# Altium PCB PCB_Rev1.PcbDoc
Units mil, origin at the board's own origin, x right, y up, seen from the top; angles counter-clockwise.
Board outline 1770 x 990 mil, 4 copper layers (Top Layer, Layer 1 (GND), Layer 2 (PWR), Bottom Layer), stack 67.556 mil thick; 55 components, 43 nets, 231 pads, 78 vias.
Unrouted connection lines stored in the file: 55.
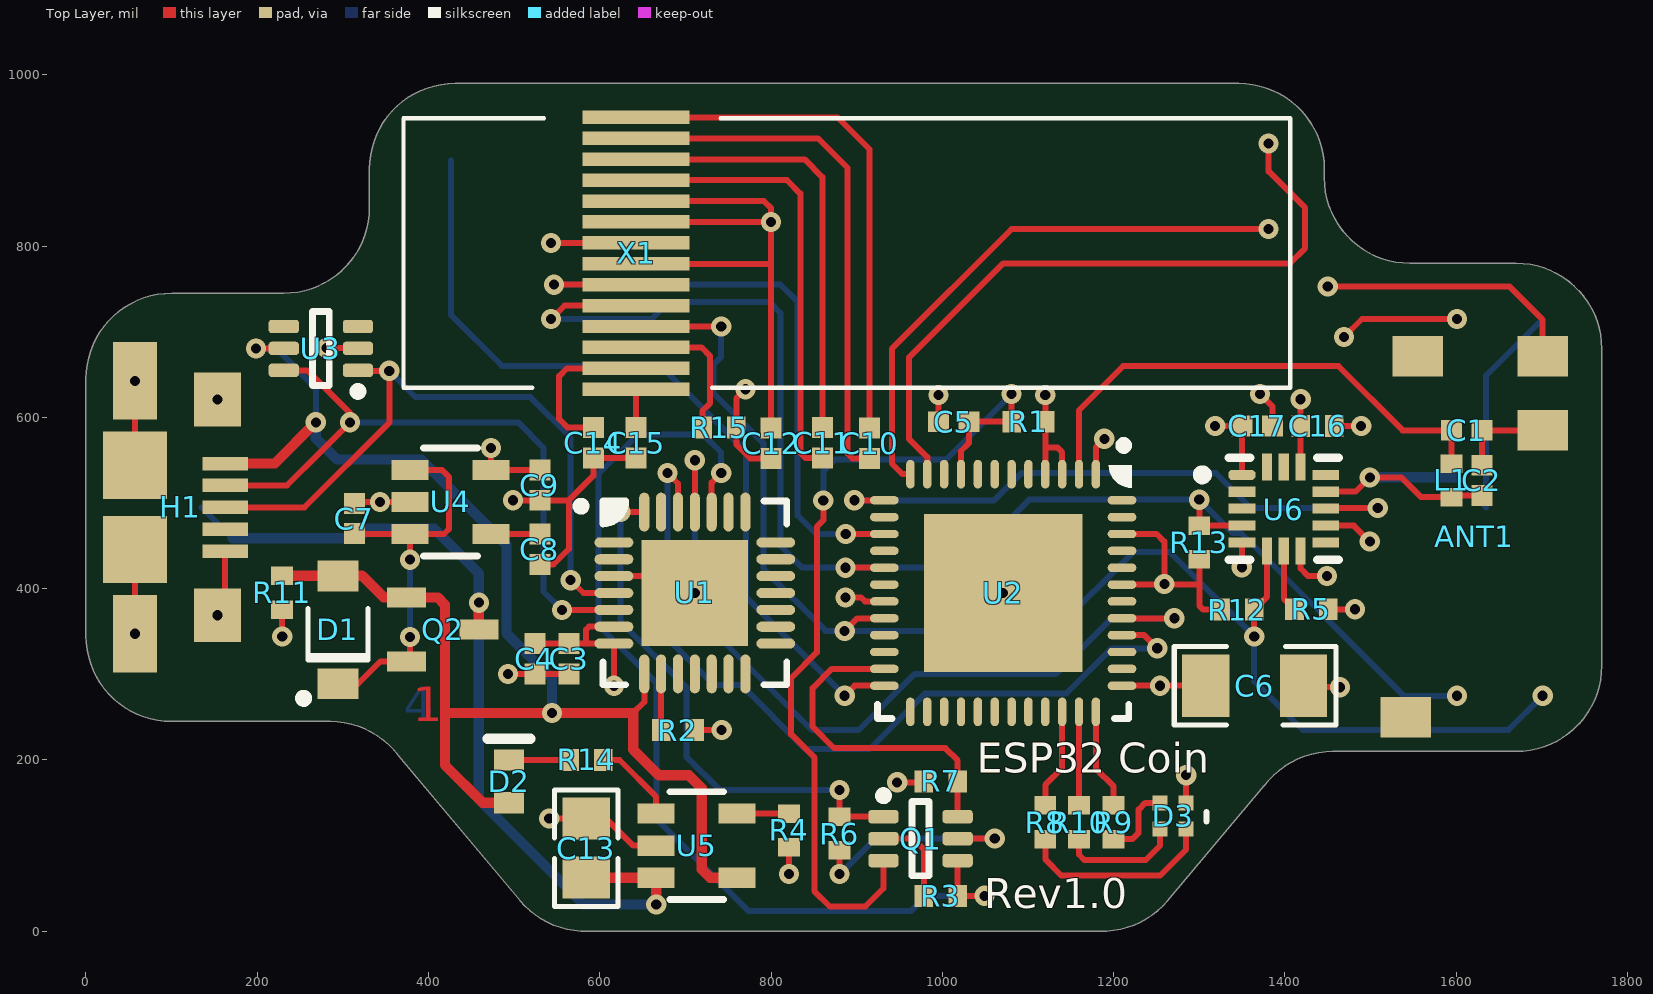
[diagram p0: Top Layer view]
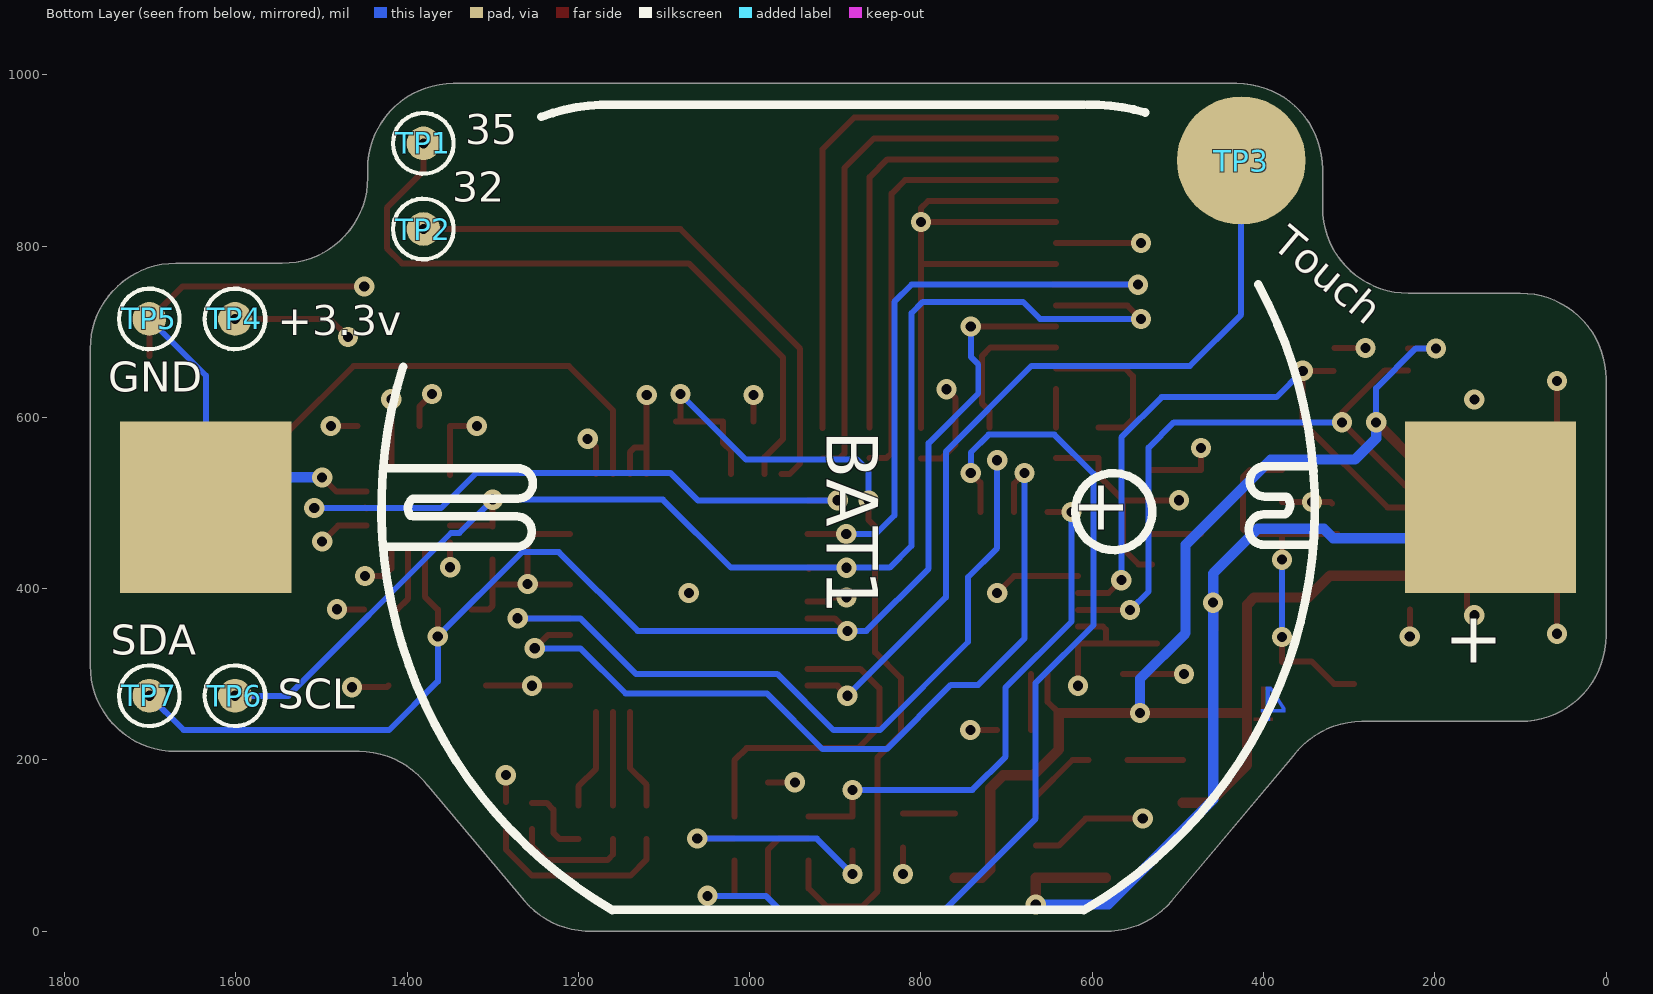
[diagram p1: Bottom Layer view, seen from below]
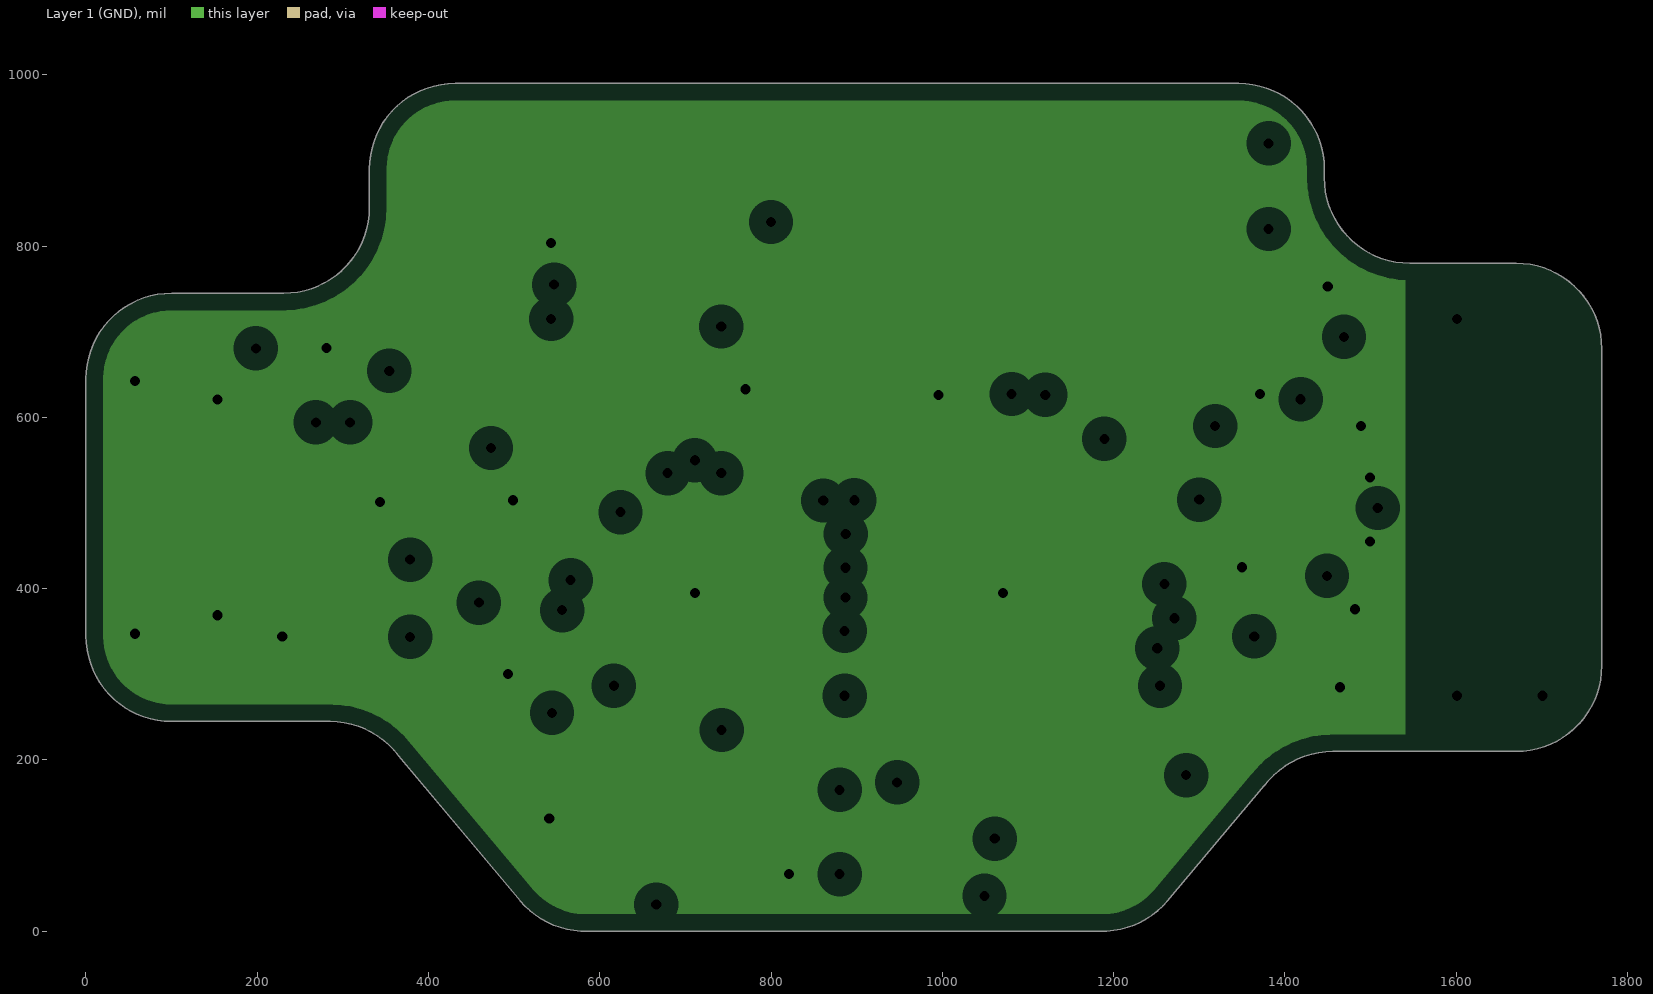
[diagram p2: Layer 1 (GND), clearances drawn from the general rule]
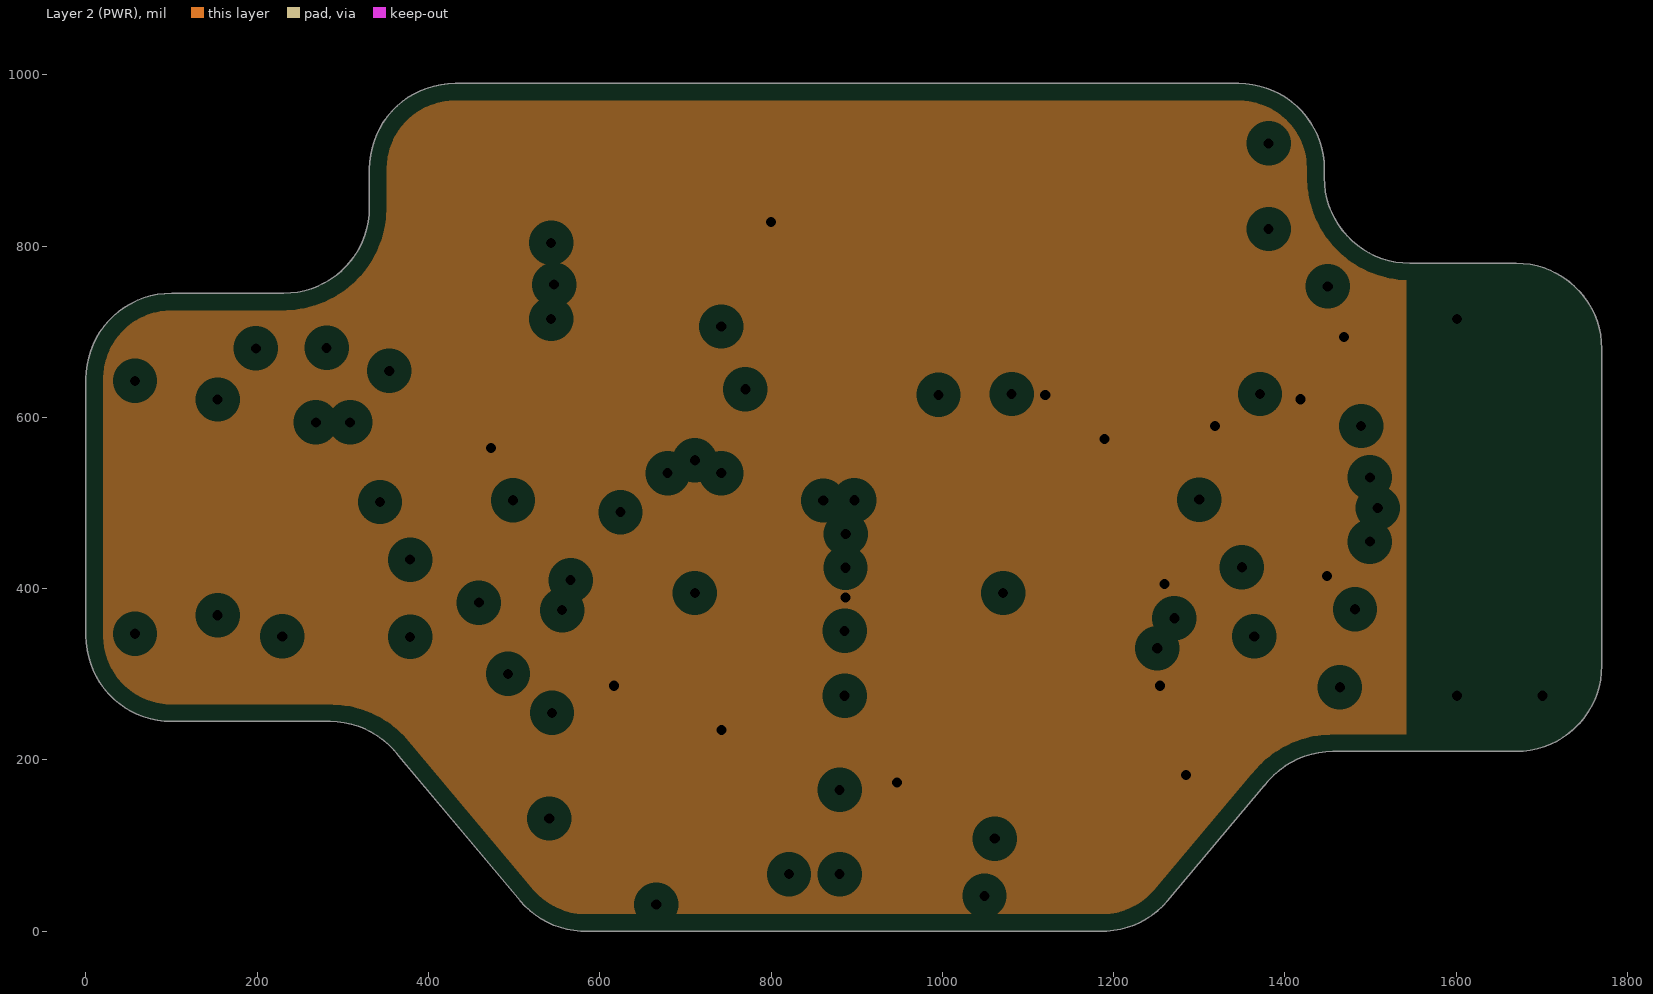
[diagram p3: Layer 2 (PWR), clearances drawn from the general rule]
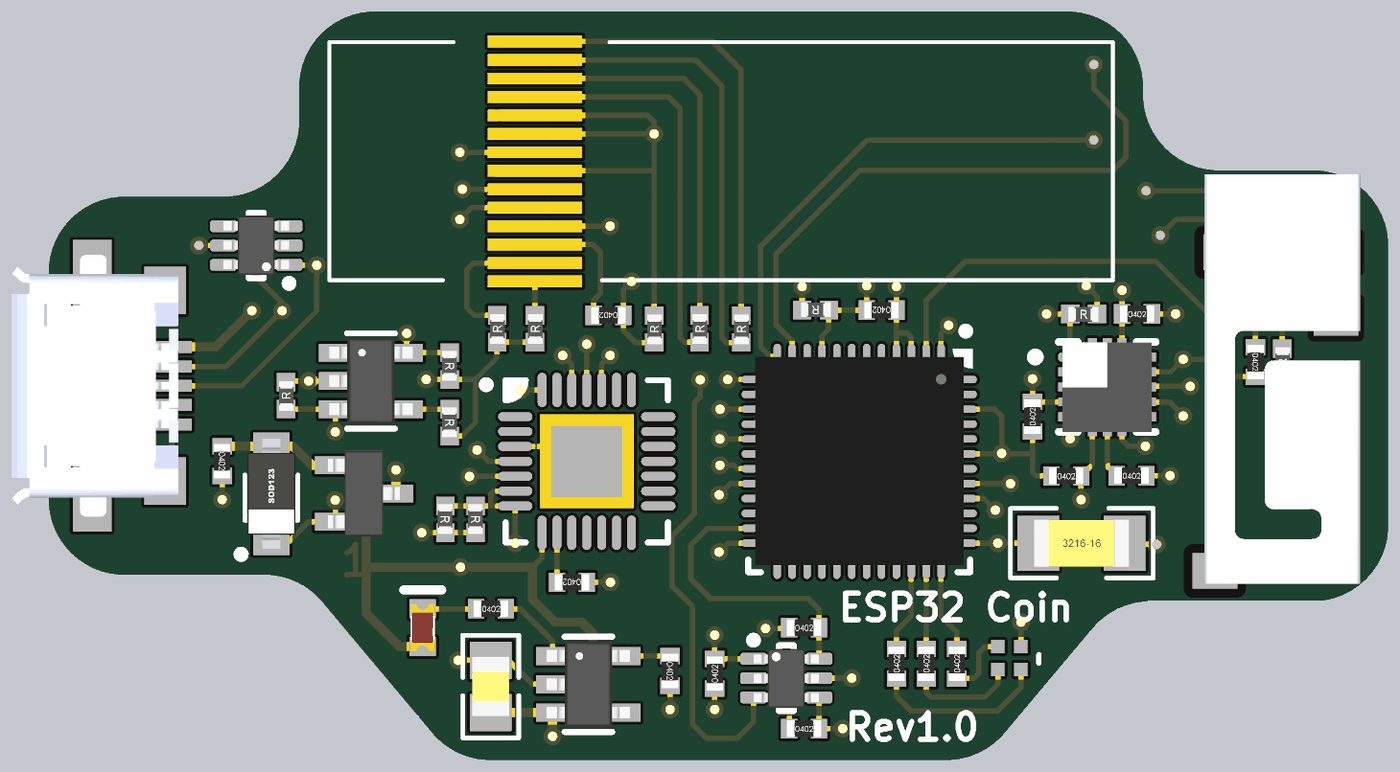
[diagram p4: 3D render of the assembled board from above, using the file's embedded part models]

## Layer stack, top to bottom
Top Solder: solder mask 0.4, Solder Resist, Dk 3.5
Top Layer: signal copper 1.4
Dielectric 2: prepreg 2.8, PP-006, Dk 4.1
Layer 1 (GND): plane copper 1.3779, net GND
Dielectric 1: dielectric 56.4, FR-4, Dk 4.8
Layer 2 (PWR): plane copper 1.3779, net +3.3V
Dielectric 3: prepreg 2.8, PP-006, Dk 4.1
Bottom Layer: signal copper 1.4
Bottom Solder: solder mask 0.4, Solder Resist, Dk 3.5

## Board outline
100,245 285,245 cw(c285,145) 365,205 507.44,35.24 506.98,35.69 ccw(c583.59,99.97) 586,0 1184,0 ccw(c1186.41,99.97) 1263.02,35.69 1262.55,35.24 1375.78,170.18 1376,170 cw(c1456,110) 1456,210 1670,210 ccw(c1670,310) 1770,310 1770,680 ccw(c1670,680) 1670,780 1546,780 cw(c1546,880) 1446,880 1446,890 ccw(c1346,890) 1346,990 431,990 ccw(c431,890) 331,890 331,845 cw(c231,845) 231,745 100,745 ccw(c100,645) 0,645 0,345 ccw(c100,345)

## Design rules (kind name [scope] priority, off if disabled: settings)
Clearance Clearance_H1 [All vs InComponent('H1')] p1: gap=9.5 ignorepadtopadclearanceinfootprint=FALSE
Clearance Clearance_U3 [All vs InComponent('U3')] p2: gap=9.5 ignorepadtopadclearanceinfootprint=FALSE
Clearance Clearance_Q1 [All vs InComponent('Q1')] p3: gap=9.5 ignorepadtopadclearanceinfootprint=FALSE
Clearance Clearance_X1 [All vs InComponent('X1')] p4: gap=8.5 ignorepadtopadclearanceinfootprint=FALSE
Clearance Clearance_U2 [All vs InComponent('U2')] p5: gap=9.5 ignorepadtopadclearanceinfootprint=FALSE
Clearance Clearance_U1 [All vs InComponent('U1')] p6: gap=7.8 ignorepadtopadclearanceinfootprint=FALSE
Clearance Clearance_U6 [All vs InComponent('U6')] p7: gap=7.5 ignorepadtopadclearanceinfootprint=FALSE
Clearance [All] p8: gap=10 ignorepadtopadclearanceinfootprint=FALSE except(0: Arc-Hole Track-Hole SMDPad-Hole THPad-Hole Via-Hole Fill-Hole Poly-Hole Region-Hole Text-Hole)
MinimumSolderMaskSliver MinimumSolderMaskSliver_X1 [All vs InComponent('X1')] p1: minsoldermaskwidth=0.6
MinimumSolderMaskSliver [All] p2: minsoldermaskwidth=1
PlaneClearance [All] p1: clearance=20
PlaneConnect [All] p1: planeconnectstyle=Relief reliefexpansion=20 reliefentries=4 reliefconductorwidth=10 reliefairgap=10
PolygonConnect [All] p1: connectstyle=Relief reliefconductorwidth=10 reliefentries=4 polygonreliefangle="90 Angle" airgapwidth=10
RoutingVias [All] p1: holewidth=11.81 width=23.62 viastyle="Through Hole" minholewidth=11.81 minwidth=23.62 maxholewidth=11.81 maxwidth=23.62
SilkToSilkClearance [All] p1: silktosilkclearance=5
SilkToSolderMaskClearance [IsPad] p1: minsilkscreentomaskgap=5 clearancetoexposedcopper=TRUE
SolderMaskExpansion [All] p1: expansion=4
Width [All] p1: maxlimit=12 minlimit=7 preferedwidth=7
25 further rules are at their usual default settings.

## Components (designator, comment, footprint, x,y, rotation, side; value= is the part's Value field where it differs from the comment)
ANT1 "RF ANT 2.4GHZ STAMPED MET SLD" PRO-OB-440 1701,671.61 r0 top locked
BAT1 "BATTERY-HOLDER (2450)" BU2450SM-JJ-GTR 885,495 r0 bottom locked value="Coin Cell Holder"
C1 "4.7pF" CAPC1005X56N 1612.28,585 r180 top
C2 "2.7pF" CAPC1005X56N 1630,526.5 r90 top
C3 "1uF" CAPC1005X56N 564.18,318.23 r270 top
C4 "1uF" CAPC1005X56N 524.18,318.23 r270 top
C5 "0.1uF" CAPC1005X56N 1013.28,595 r180 top
C6 "100uF" CAPC3216X160N 1364.78,286.73 r0 top
C7 "1uF" CAPC1005X56N 313.43,481.96 r90 top
C8 "10nF" CAPC1005X56N 530,446.18 r270 top
C9 "2.2uF" CAPC1005X56N 530,520.98 r270 top
C10 "1uF" CAPC1005X56N 915,570 r90 top
C11 "1uF" CAPC1005X56N 860,570.43 r90 top
C12 "1uF" CAPC1005X56N 800,570 r90 top
C13 "10uF" CAPC2012X140N 584.18,97.05 r90 top
C14 "4.7uF" CAPC1005X56N 592.5,570.43 r90 top
C15 "2.2uF" CAPC1005X56N 642.5,570.43 r90 top
C16 "0.1uF" RESC1005X40L 1438.08,590 r0 top
C17 "0.1uF" CAPC1005X56N 1367.61,590 r0 top
D1 "MBR0520-TP" SOD123 294.18,352 r90 top value=MBR0520
D2 "LED_0603" LED1608X55N-RED 494.18,175 r270 top value=Red
D3 "RGB" FC-B1010RGBT-HG 1269.44,134.67 r0 top
H1 "Micro USB" 1981584-1 110,495 r270 top locked
L1 "Inductor" RESC1005X40L 1594.57,526.5 r270 top value=1.8nH
Q1 "BC847S" SOT65P210X110-6N 974.57,107.21 r0 top
Q2 "FDN340P" SOT95P240X110-3N 416.51,352.4 r0 top value="Mosfet P-H"
R1 "10K" RESC1005X40L 1100.53,595 r180 top
R2 "1K" RESC1005X40L 691.31,235 r180 top
R3 "10K" RESC1005X40L 998.19,41.38 r0 top
R4 "10K" RESC1005X40L 821,117.72 r270 top
R5 "10K" RESC1005X40L 1430.87,376 r0 top
R6 "10K" RESC1005X40L 880,114.09 r90 top
R7 "10K" RESC1005X40L 998.19,175 r0 top
R8 "1K" RESC1005X40L 1120.21,127.28 r90 top
R9 "1K" RESC1005X40L 1200,127.28 r90 top
R10 "1K" RESC1005X40L 1159.58,127.28 r90 top
R11 "100K" RESC1005X40L 229.18,395.32 r270 top
R12 "4.7K" RESC1005X40L 1344.5,375.63 r0 top
R13 "4.7K" RESC1005X40L 1300,454.06 r90 top
R14 "2K" RESC1005X40L 584.5,200 r0 top
R15 "390K" RESC1005X40L 739.68,588.15 r180 top
TP1 "Test Point, 1mm Top Layer" TP100TL#1 1381,920 r90 bottom
TP2 "Test Point, 1mm Top Layer" TP100TL#1 1381,820 r90 bottom
TP3 "Test Point, 1mm Top Layer" TP100TL#2 401,925 r90 bottom
TP4 "Test Point, 1mm Top Layer" TP100TL#1 1601,715 r90 bottom
TP5 "Test Point, 1mm Top Layer" TP100TL#1 1701,715 r90 bottom
TP6 "Test Point, 1mm Top Layer" TP100TL#1 1601,275 r90 bottom
TP7 "Test Point, 1mm Top Layer" TP100TL#1 1701,275 r90 bottom
U1 "CP2102N" 28-QFN 711,395 r0 top
U2 "ESP32-PICO-D4" QFN48 1071,395 r270 top
U3 "PESD5V0L5UY" SOT65P210X110-6N 274.31,681.57 r180 top
U4 "SE5218ALG-LF" SOT95P280X144-5N 425.8,501.3 r0 top
U5 "SL4054ST25P" SOT95P280X144-5N 713.13,100 r0 top
U6 "ACCEL" QFN3X3_16_1.2 1398.68,492.99 r0 top
X1 "OLED_GLASS 96x16" "OLED_GLASS 96x16" 370.85,634.53 r180 top locked

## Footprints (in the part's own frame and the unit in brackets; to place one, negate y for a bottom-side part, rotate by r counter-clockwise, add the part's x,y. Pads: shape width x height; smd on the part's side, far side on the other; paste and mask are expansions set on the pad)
28-QFN [mm] "QFN, 28-Leads, Body 5.00x5.00mm, Pitch 0.50mm, Thermal Pad 3.15x3.15mm, IPC Medium Density"
  oval 1.15x0.3 smd: 1(-2.4,1.5) 2(-2.4,1) 3(-2.4,0.5) 4(-2.4,0) 5(-2.4,-0.5) 6(-2.4,-1) 7(-2.4,-1.5) 15(2.4,-1.5) 16(2.4,-1) 17(2.4,-0.5) 18(2.4,0) 19(2.4,0.5) 20(2.4,1) 21(2.4,1.5)
  oval 0.3x1.15 smd: 8(-1.5,-2.4) 9(-1,-2.4) 10(-0.5,-2.4) 11(0,-2.4) 12(0.5,-2.4) 13(1,-2.4) 14(1.5,-2.4) 22(1.5,2.4) 23(1,2.4) 24(0.5,2.4) 25(0,2.4) 26(-0.5,2.4) 27(-1,2.4) 28(-1.5,2.4)
  rect 3.15x3.15 smd paste-0.381: 29(0,0)
  silkscreen extent -3.5,-2.73 2.73,2.73, body extent -2.58,-2.57 2.57,2.58, height 1
1981584-1 [mm] "CONN RCPT MICRO USB TYPE AB"
  rect 0.4x1.35 smd: 1(-1.3,1.338) 2(-0.65,1.338) 3(0,1.338) 4(0.65,1.338) 5(1.3,1.338)
  rect 2.3x1.3 smd: 6(-3.75,-1.337) 6(3.75,-1.337)
  rect 1.6x1.4 smd: 6(-3.2,1.113) 6(3.2,1.113)
  rect 2x1.9 smd: 6(-1.25,-1.337) 6(1.25,-1.337)
  body extent -4.4,-4.05 4.4,1.55, height 2.75
BU2450SM-JJ-GTR [mil] "HOLDER,BATT,COIN,24.5MM,SMT"
  rect 200x200 smd: 1(-750,0) 2(750,0)
  silkscreen extent -545,-470 545,470, body extent -842,-570 3485,485, height 291
CAPC1005X56N [mm] "Chip Capacitor, 2-Leads, Body 1.0x0.5mm, IPC Medium Density (0402 ceramic)"
  rect 0.62x0.62 smd: 1(-0.45,0) 2(0.45,0)
  body extent -0.55,-0.3 0.55,0.3, height 0.6
CAPC2012X140N [mm] "Chip Capacitor, 2-Leads, Body 2.0x1.3mm, IPC Medium Density (0805 ceramic)"
  rect 1.25x1.4 smd: 1(-0.875,0) 2(0.875,0)
  silkscreen extent -1.73,-0.94 1.73,0.94, body extent -1,-0.62 1,0.63, height 1.24
CAPC3216X160N [mm] "Chip Capacitor, 2-Leads, Body 3.2x1.6mm, IPC Medium Density(C1206)"
  rect 1.4x1.85 smd: 1(-1.45,0) 2(1.45,0)
  silkscreen extent -2.39,-1.17 2.41,1.17, body extent -1.6,-0.8 1.6,0.8, height 1.89
FC-B1010RGBT-HG [mm] "LED,RGB,SMD,RoHS"
  rect 0.45x0.45 smd: 1(0.387,0.388) 2(0.387,-0.387) 3(-0.387,-0.387) 4(-0.387,0.388)
  silkscreen extent 0.99,-0.16 0.99,0.12, body extent -0.53,-0.55 0.53,0.58, height 1.2
LED1608X55N-RED [mil] "Chip LED RED, 2-Leads, Body 1.6x0.8mm, IPC Medium Density (0603 med)"
  rect 25x35 smd: 1(-25,0) 2(25,0)
  silkscreen extent -50,-25 -50,25, body extent -31,-16 31,16, height 24
"OLED_GLASS 96x16" [mm] "OLED_GLASS 96x16"
  rect 3.175x0.4 smd paste-2.54: 1(-6.9,-8.02) 2(-6.9,-7.4) 3(-6.9,-6.78) 4(-6.9,-6.16) 5(-6.9,-5.54) 6(-6.9,-4.92) 7(-6.9,-4.3) 8(-6.9,-3.68) 9(-6.9,-3.06) 10(-6.9,-2.44) 11(-6.9,-1.82) 12(-6.9,-1.2) 13(-6.9,-0.58) 14(-6.9,0.04)
  silkscreen extent -26.3,-8 0,0, body extent -26.3,-8 0,0, height 2
PRO-OB-440 [mm] "RF ANT 2.4GHZ STAMPED MET SLD"
  rect 1.5x1.2 smd mask+0.2: 1(0,0) 2(0,-2.2)
  rect 1.5x1.2 smd mask+0.3: 3(-3.7,0) 4(-4.064,-10.709)
  body extent -4.42,-11.14 7.98,2.61, height 3.56
QFN3X3_16_1.2 [mm] "QFN3X3_16_1.2"
  oct 0.8x0.3 smd: 1(-1.245,1.016)
  rect 0.8x0.3 smd: 2(-1.245,0.514) 3(-1.245,0.013) 4(-1.245,-0.489) 5(-1.245,-0.991) 9(1.245,-0.991) 10(1.245,-0.489) 11(1.245,0.013) 12(1.245,0.514) 13(1.245,1.016)
  rect 0.3x0.8 smd: 6(-0.495,-1.245) 7(0,-1.245) 8(0.495,-1.245) 14(0.495,1.245) 15(0,1.245) 16(-0.495,1.245)
  silkscreen extent -2.54,-1.5 1.63,1.52, body extent -1.51,-1.5 1.51,1.5, height 0.81
QFN48 [mm] "QFN, 48-Leads, Body 7x7mm, Pitch 0.5mm, IPC Medium Density"
  oval 0.85x0.25 smd: 1(-3.525,2.75) 2(-3.525,2.25) 3(-3.525,1.75) 4(-3.525,1.25) 5(-3.525,0.75) 6(-3.525,0.25) 7(-3.525,-0.25) 8(-3.525,-0.75) 9(-3.525,-1.25) 10(-3.525,-1.75) 11(-3.525,-2.25) 12(-3.525,-2.75) 25(3.525,-2.75) 26(3.525,-2.25) 27(3.525,-1.75) 28(3.525,-1.25) 29(3.525,-0.75) 30(3.525,-0.25) 31(3.525,0.25) 32(3.525,0.75) 33(3.525,1.25) 34(3.525,1.75) 35(3.525,2.25) 36(3.525,2.75)
  oval 0.25x0.85 smd: 13(-2.75,-3.525) 14(-2.25,-3.525) 15(-1.75,-3.525) 16(-1.25,-3.525) 17(-0.75,-3.525) 18(-0.25,-3.525) 19(0.25,-3.525) 20(0.75,-3.525) 21(1.25,-3.525) 22(1.75,-3.525) 23(2.25,-3.525) 24(2.75,-3.525) 37(2.75,3.525) 38(2.25,3.525) 39(1.75,3.525) 40(1.25,3.525) 41(0.75,3.525) 42(0.25,3.525) 43(-0.25,3.525) 44(-0.75,3.525) 45(-1.25,3.525) 46(-1.75,3.525) 47(-2.25,3.525) 48(-2.75,3.525)
  rect 4.7x4.7 smd paste-0.5: 49(0,0)
  silkscreen extent -4.5,-3.72 3.72,3.81, body extent -3.52,-3.51 3.5,3.51, height 0.78
RESC1005X40L [mm] "Chip Resistor, 2-Leads, Body 1.0x0.5mm, IPC Medium Density (0402)"
  rect 0.55x0.65 smd: 1(-0.5,0) 2(0.5,0)
  body extent -0.57,-0.27 0.58,0.28, height 0.41
SOD123 [mil] "Molded Diode, 2-Leads, Body 2.85x1.8mm, IPC Medium Density (SOD123)"
  rect 36x48 smd: 1(-63,0) 2(63,0)
  silkscreen extent -85,-35 25,45, body extent -73,-31 73,31, height 50
SOT65P210X110-6N [mm] "SC70, 6-Leads, Body 2.4x2.2mm (max), Pitch 0.65mm, IPC Medium Density"
  rrect50% 0.9x0.4 smd mask+0.076: 1(-1.1,0.675) 2(-1.1,0.025) 3(-1.1,-0.625) 4(1.1,-0.625) 5(1.1,0.025) 6(1.1,0.675)
  silkscreen extent -1.22,-1.07 0.25,1.42, body extent -1.1,-0.97 1.1,1.01, height 0.99
SOT95P240X110-3N [mm] "SOT23, 3-Leads, Body 3.0x2.5mm (max), Pitch 0.95mm, IPC Medium Density"
  rect 1.15x0.6 smd: 1(-1.075,0.95) 2(-1.075,-0.95) 3(1.075,0)
  body extent -1.2,-1.45 1.2,1.45, height 0.99
SOT95P280X144-5N [mm] "SOT23, 5-Leads, Body 3.1x3.0mm (max), Pitch 0.95mm, IPC Medium Density (RFMD SOT23-5)"
  rect 1.1x0.6 smd: 1(-1.2,0.95) 2(-1.2,0) 3(-1.2,-0.95) 4(1.2,-0.95) 5(1.2,0.95)
  silkscreen extent -0.8,-1.6 0.8,1.6, body extent -1.4,-1.45 1.4,1.45, height 1.45
TP100TL#1 [mm] "Test Point"
  round 1 smd paste-0.5 mask+0.076: 1(0,0)
  silkscreen extent -0.9,-0.9 0.9,0.9
TP100TL#2 [mm] "Test Point"
  round 3.81 smd paste-0.5 mask+0.076: 1(-0.635,0.635)

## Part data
ANT1: library part PRO-OB-440, Manufacturer="Proant AB"
BAT1: library part BU2450SM-JJ-GTR, "HOLDER,BATT,COIN,24.5MM,SMT", Manufacturer=MPD
C1: library part CAP_0402, "CAP CER 47pF 50V 0402", Manufacturer=Huaxin, PartNumber=0603N4R7C500CT
C2: library part CAP_0402, "CAP CER 2.7pF 50V 0402", Manufacturer=Huaxin, PartNumber=0603N2R7C500
C3 C4 C7 C10 C11 C12: library part CAP_0603, "CAP CER 1uF 16V 0402", Manufacturer=Murata, PartNumber=GRM155R61C105KA12D
C5 C16 C17: library part CAP_0402, "CAP CER 0.1uF 16V 0402", Manufacturer=CCTC, PartNumber=TCC0402X5R104M160AT
C6: library part CAP_1206, "CAP CER 100uF 6.3V 1206", Manufacturer="Taiyo Yuden", PartNumber=JMK316BJ107ML-T
C8: library part CAP_0603, "CAP CER 10nF 0402", Manufacturer=Murata, PartNumber=GRM155R71C103JA01D
C9 C15: library part CAP_0402, "CAP CER 2.2uF 16V 0402", Manufacturer=Samsung, PartNumber=CL05A225KO5NQNC
C13: library part CAP_0805, "CAP CER 10uF 16V 0805", Manufacturer=Samsung, PartNumber=CL21A106KOQNNNG
C14: library part CAP_0603, "CAP CER 4.7uF 16V 0402", Manufacturer=Kyocera, PartNumber=CM05X5R475M16AH
D1: "DIODE SCHOTTKY 20V 500MA SOD123", Manufacturer=CJ, PartNumber=MBR0520
D2: "LED RED CLEAR 0603 SMD", Manufacturer=FNO, PartNumber=FC-DA1608HRK-620D
D3: library part FC-B1010RGBT-HG, "LED,RGB,SMD,RoHS", Manufacturer=Foshan
H1: library part 1981584-1, "CONN RCPT MICRO USB TYPE AB", Manufacturer="REG CON", PartNumber=C21377
L1: "Inductor 1.8nH 0402", Manufacturer=GFBE, PartNumber=BKW0603UC1N8KGT
Q1: "TRANS 2NPN 44V 0.1A SC-70-6", Manufacturer=Changjiang
Q2: "MOSFET P-CH 20V 2A SOT-23", Manufacturer="On Semi"
R1 R3 R6 R7: library part RES_0402, "RES SMD 10K OHM 0402", Manufacturer=Guangdong, PartNumber=RC-02W1002FT
R2: library part RES_0603, "RES SMD 1K OHM 0402", Manufacturer=Yageo, PartNumber=RC0402FR-071KL
R4: library part RES_0603, "RES SMD 10K OHM 1% 1/10W 0402", Manufacturer=Guangdong, PartNumber=RC-02W1002FT
R5: library part RES_0603, "RES SMD 10K OHM 0402", Manufacturer=Guangdong, PartNumber=RC-02W1002FT
R8 R9 R10: library part RES_0402, "RES SMD 1K OHM 1% 1/10W 0402", Manufacturer=Yageo, PartNumber=RC0402FR-071KL
R11: library part RES_0603, "RES SMD 100K OHM 0402", Manufacturer="Uniroyal Elec", PartNumber=0402WGF1003TCE
R12: library part RES_0603, "RES SMD 4.7K OHM 0402", Manufacturer="TA-I Tech", PartNumber=RM04FTN4701
R13: library part RES_0603, "RES SMD 4.7K OHM 0402", Manufacturer="HK Resistors", PartNumber=RM04FTN4701
R14: library part RES_0603, "RES SMD 2K OHM 1% 1/10W 0402", Manufacturer="LIZ Elec", PartNumber=CR0402FF2001G
R15: library part RES_0603, "RES SMD 390K OHM 0402", Manufacturer=Guangdong, PartNumber=RC-02W3903FT
TP1 TP2 TP3 TP4 TP5 TP6 TP7: Manufacturer=N/A
U1: "IC BRIDGE USB TO UART 28QFN", Manufacturer="Silicon Labs", PartNumber=CP2102N-A01-GQFN28
U2: "RF Transceiver ICs QFN-48_7x7x05P RoHS", Manufacturer=Espressif
U3: "TVS SOT-363 RoHS", Manufacturer=Yenji
U4: "IC REG LDO 3.3V 0.5A SOT23-5", Manufacturer=Seaward
U5: "Charger IC Lithium-Ion/Polymer SOT23-5", Manufacturer=Techfuse
U6: library part E-05-177, "IC,ACCEL,2-16G I2C/SPI,16LGA,RoHS"
X1: "96x16 OLED_GLASS", Manufacturer=N/A, PartNumber=ER-OLED0.69-1W

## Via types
v1: diameter 23.62, hole 11.81, Top Layer to Bottom Layer, tented both sides, 77 vias
v2: diameter 23.62, hole 11.81, Top Layer to Bottom Layer, 1 vias

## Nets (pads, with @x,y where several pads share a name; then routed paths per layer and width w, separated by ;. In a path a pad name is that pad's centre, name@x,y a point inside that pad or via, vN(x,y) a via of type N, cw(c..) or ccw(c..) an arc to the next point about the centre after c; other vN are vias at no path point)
+3.3V: C3.1 C4.1 C6.1 C9.1 C12.2 C16.1 C17.1 D3.1 R1.1 R2.1 R7.1 R12.1 R13.1 TP4.1 U1.6 U1.7 U2.1 U2.3 U2.4 U2.19 U2.37 U2.43 U2.46 U4.5 U6.1 U6.8 U6.14 X1.5 X1.6 X1.8 | length 2069
  Top Layer w7: v1(473.05,564.25) U4.5 C9.1 ; C4.1 C3.1 584.18,335.95 ; v1(616.51,286.73) U1.7 584.18,335.95 ; U1.6 587.41,355.63 584.18,352.4 584.18,335.95 ; X1.8 798.31,779.41 800,777.72 ; X1.6 v1(800,828.23) ; X1.5 791.76,852.64 800,844.4 v1(800,828.23) ; R2.1 v1(742.3,235) ; C12.2 v1(800,828.23) ; v1(886.88,389.8) 905.21,389.8 909.85,385.16 U2.19 ; v1(947.26,173.9) R7.1@978.56,173.9 ; U2.4 1120.21,565 ; v1(1120.21,626.3) R1.1 1120.21,565 ; U2.3 1139.9,559.29 1134.18,565 1120.21,565 ; U2.1 1179.27,565.08 v1(1189.18,575) ; U2.37 C6.1 ; U2.43 1300,404.84 ; U2.46 1250.29,463.9 1259.18,455 v1(1259.18,405.5) ; D3.1@1284.7,151.02 v1(1284.7,182.32) ; R13.1 1300,380.19 1304.56,375.63 R12.1 ; v1(1318.6,590) C17.1 1349.68,589.79 U6.1 ; U6.8 1418.18,423.68 1426.87,415 v1(1449.18,415) ; U6.14 1418.18,589.79 C16.1 v1(1418.4,621.3) ; v1(1469,694) 1490,715 v1(1601,715)
  other v1: 1254.18,286.73
BLUE: R8.2 U2.34 | length 117.4
  Top Layer w7: R8.2 1120.21,171.03 1139.9,190.71 U2.34
D+: H1.3 U1.4 U3.1 | length 800.9
  Top Layer w7: H1.3 255.19,495 354.18,594 v1(354.18,654.41) U3.1@318.2,654.41 ; v1@570.6,410 v1(566,410) 581,395 U1.4
  Bottom Layer w7: v1(354.18,654.41) 384.89,623.7 518.97,623.7 566,576.68 v1(566,410)
D-: H1.2 U1.5 U3.6 | length 790.8
  Top Layer w7: H1.2 234.78,520.59 273.43,559.25 v1(308.43,594.25) 308.43,604.97 258.4,655 U3.6 ; v1(556,375) 616.2,375 U1.5
  Bottom Layer w7: v1(308.43,594.25) 504.73,594.25 534.18,564.79 534.18,396.81 v1(556,375) v1@556,383.19
DTR: Q1.1 R6.2 U1.28 | length 622.7
  Top Layer w7: v1(624.18,489.49) U1.28 ; v1(880,165.08) R6.2 Q1.1
  Bottom Layer w7: v1(624.18,489.49) 624.18,361.62 701,284.8 701,204 739.92,165.08 v1(880,165.08)
EN: C5.1 Q1.3 R1.2 U2.9 | length 1054.8
  Top Layer w7: v1(861,503) 861,480 853.56,472.56 853.56,325.68 823.56,295.68 823.56,230 850.56,203 850.56,46.9 868.56,28.9 910,28.9 931.26,50.16 Q1.3 ; U2.9 1021.79,560.79 1031,570 C5.1 R1.2 R1.2@1085.84,595 ; R1.2@1080.84,596.1 v1(1080.84,627.4)
  Bottom Layer w7: v1(861,503) 861,537.24 874.56,550.81 1004.25,550.81 v1(1080.84,627.4)
GND: ANT1.1 BAT1.2 C2.1 C3.2 C4.2 C5.2 C6.2 C7.2 C8.2 C9.2 C12.1 C13.2 C14.1 C15.1 C16.2 C17.2 H1.5 H1.6 L1.2 R4.2 R5.2 R11.2 R15.1 TP5.1 U1.3 U1.29 U2.49 U3.2 U4.2 U5.2 U6.5 U6.10 U6.12 X1.7 | length 2411
  Top Layer w7: v1(57.34,347.36) H1.6@57.34,445.79 ; H1.6@57.34,544.21 v1(57.34,642.64) ; v1(153.8,369.02) 162.66,377.87 H1.5 ; v1(229.18,344.33) R11.2 ; v1(281.04,681.18) U3.2@317.02,681.18 ; C7.2@319.91,499.25 321.97,501.3 U4.2 ; v1(492.89,300.51) C4.2 C3.2 ; v1(498.7,503.27) C9.2 563.87,503.27 ; C8.2 545.96,428.46 563.87,446.37 563.87,503.27 ; v1(541,131.73) 583.95,131.73 C13.2 607.69,131.5 639.18,100 U5.2 ; v1(543.18,803.82) X1.7 ; U1.3 691.31,414.69 v1(711,395) ; C15.1 C14.1 592.5,531.9 563.87,503.27 ; v1(770.06,632.95) 759.37,622.27 R15.1 759.37,568.4 775.49,552.28 C12.1 ; v1(821,66.73) R4.2 ; C5.2 v1(995.57,626.3) ; v1(1349.68,425.03) U6.5 ; v1(1370.92,627.4) 1385.33,612.99 C17.2 ; C6.2 1423.6,285 v1(1464.18,285) ; U6.10 1480.44,473.74 v1(1499.18,455) ; U6.12 1482.43,513.24 v1(1499.18,530) 1536,530 1559.19,506.81 L1.2 1596.54,508.78 C2.1 ; v1(1450,753) 1662,753 1701,714 ANT1.1 ; R5.2 v1(1481.85,376) ; C16.2 v1(1489.07,590)
  Bottom Layer w7: BAT1.2@1600,530 BAT1.2 1635,649 TP5.1
  Bottom Layer w12: v1(1499.18,530) BAT1.2@1600,530
  other v1: 343.43,501.3 153.8,620.98
  other v2: 1071,395
GPIO32: TP2.1 U2.12 | length 658.6
  Top Layer w7: U2.12 953.48,533.78 941,546.26 941,680 1081,820 v1(1381,820)
GPIO35: TP1.1 U2.11 | length 800.4
  Top Layer w7: U2.11 982.42,553.58 961,575 961,669.7 1071.3,780 1406,780 1423.6,797.6 1423.6,844.8 1381,887.4 v1(1381,920)
GREEN: R10.2 U2.35 | length 109.3
  Top Layer w7: R10.2 U2.35
INT1: U2.13 U6.11 | length 738.4
  Top Layer w7: v1(897.22,503.27) U2.13 ; U6.11 U6.11@1448.44,494.25 ; U6.11@1449.19,495 U6.11@1448.44,494.25 ; v1(1508.43,494.25) U6.11@1448.44,494.25
  Bottom Layer w7: v1(897.22,503.27) 1060.55,503.27 1092.28,535 1319.49,535 1360.24,494.25 v1(1508.43,494.25)
IO0: Q1.6 R7.2 U2.23 | length 389.4
  Top Layer w7: U2.23 871.08,306.42 848.56,283.9 848.56,238.9 873.56,213.9 1003.56,213.9 1017.87,199.58 R7.2 Q1.6
NetANT1_2: ANT1.2 C1.1 C2.2 | length 111.8
  Top Layer w7: C2.2 C1.1 ANT1.2
NetC1_2: C1.2 L1.1 U2.2 | length 600.8
  Top Layer w7: U2.2 1159.58,608.35 1211.23,660 1462.46,660 1537.46,585 C1.2 L1.1
NetC8_1: C8.1 U4.4 | length 57
  Top Layer w7: U4.4 C8.1
NetC10_1: C10.1 X1.2 | length 622.5
  Top Layer w7: X1.2 854.78,925.87 889.3,891.35 889.3,557.99 895,552.28 C10.1
NetC10_2: C10.2 X1.1 | length 613.3
  Top Layer w7: X1.1 877.87,950.28 915,913.15 C10.2
NetC11_1: C11.1 X1.4 | length 529.3
  Top Layer w7: X1.4 818.6,877.05 834.3,861.35 834.3,558.42 840,552.72 C11.1
NetC11_2: C11.2 X1.3 | length 518.6
  Top Layer w7: X1.3 839.19,901.46 860,880.65 C11.2
NetC14_2: C14.2 X1.13 | length 188
  Top Layer w7: C14.2 562.5,588.15 552.5,598.15 552.5,648.15 561.71,657.36 X1.13
NetC15_2: C15.2 X1.14 | length 44.8
  Top Layer w7: C15.2 X1.14
NetD2_1: D2.1 R14.1 | length 64.8
  Top Layer w7: D2.1 R14.1@559,200
NetD3_2: D3.2 R8.1 | length 232.5
  Top Layer w7: R8.1 1120.21,83.97 1139.18,65 1254.18,65 1284.7,95.51 D3.2
NetD3_3: D3.3 R10.1 | length 141.6
  Top Layer w7: R10.1 1159.58,89.6 1165.91,83.27 1237.46,83.27 1254.18,100 D3.3
NetD3_4: D3.4 R9.1 | length 87.5
  Top Layer w7: R9.1 1221.78,107.6 1229.18,115 1229.18,141.97 1237.14,149.92 D3.4
NetQ1_2: Q1.2 R3.1 | length 106.7
  Top Layer w7: Q1.2 966,108.19 978.5,95.68 R3.1
NetQ1_5: Q1.5 R6.1 | length 269.3
  Top Layer w7: v1(880,66.73) R6.1 ; Q1.5 v1(1061.16,108.19)
  Bottom Layer w7: v1(880,66.73) 921.46,108.19 v1(1061.16,108.19)
NetR2_2: R2.2 U1.9 | length 65.5
  Top Layer w7: R2.2 U1.9
NetR4_1: R4.1 U5.5 | length 60.6
  Top Layer w7: U5.5 R4.1
NetR5_1: R5.1 U6.7 | length 73.2
  Top Layer w7: U6.7 1398.68,388.5 R5.1
NetR14_2: R14.2 U5.1 | length 99.2
  Top Layer w7: R14.2 622.97,200 665.88,157.09 U5.1
NetR15_2: R15.2 X1.12 | length 177.7
  Top Layer w7: X1.12 718.72,681.77 728.88,671.61 728.88,616.59 720,607.72 R15.2
OLED_RESET: U2.15 X1.9 | length 751.6
  Top Layer w7: v1(546.68,755) X1.9@646,755 ; v1(887.18,463.9) U2.15
  Bottom Layer w7: v1(546.68,755) 811,755 831,735 831,485.5 852.6,463.9 v1(887.18,463.9)
RED: R9.2 U2.36 | length 117.8
  Top Layer w7: U2.36 1179.27,189.92 1200,169.19 R9.2
RTS: Q1.4 R3.2 U1.24 | length 1183.4
  Top Layer w7: U1.24 730.68,523.86 v1(741.82,535) ; Q1.4 R3.2 v1(1049.17,41.38)
  Bottom Layer w7: v1(741.82,535) 741.82,559.09 720.92,580 644.18,580 598.56,534.37 598.56,357.44 666,290 666,131.44 773.55,23.9 963.56,23.9 981.04,41.38 v1(1049.17,41.38)
RXD: U1.26 U2.40 | length 973.1
  Top Layer w7: v1(679.18,535) 691.31,522.87 U1.26 ; U2.40 1235.6,345.79 v1(1250.92,330.47) v1@1250.92,338.27
  Bottom Layer w7: v1(679.18,535) 679.18,341.62 733.09,287.72 765,287.72 840,212.72 915,212.72 980,277.72 1145,277.72 1197.76,330.47 v1(1250.92,330.47)
SCL: R13.2 TP6.1 U2.17 U6.4 X1.10 | length 1715.2
  Top Layer w7: v1(543.18,715) 558.77,730.59 X1.10 ; v1(886.88,424.53) U2.17@931.92,424.53 ; U2.17@930.96,423.27 U2.17 ; R13.2@1300,472.72 R13.2 ; v1(1300,504.02) R13.2 ; U6.4 R13.2
  Bottom Layer w7: v1(543.18,715) 660.88,715 680.88,735 797.72,735 811,721.72 811,450.03 836.5,424.53 v1(886.88,424.53) 1021.81,424.53 1101.3,504.02 v1(1300,504.02) 1339.02,465 1348.72,465 1538.72,275 v1(1601,275)
SDA: R12.2 TP7.1 U2.20 U6.6 X1.11 | length 1682
  Top Layer w7: X1.11 v1(741.82,706.18) ; v1@885.92,353.15 v1(885.92,350.71) 900.68,365.47 U2.20 ; v1(1364.18,344.33) R12.2 1379.18,390.63 U6.6
  Bottom Layer w7: v1(741.82,706.18) 741.82,670.82 733.09,662.09 733.09,627.91 791,570 791,423.46 863.76,350.71 v1(885.92,350.71) 1130.71,350.71 1222.72,442.72 1265.8,442.72 v1(1364.18,344.33) 1364.18,291.81 1421,235 1661,235 v1(1701,275)
TOUCH: TP3.1 U2.24 | length 975
  Top Layer w7: v1(885.92,275) 897.65,286.73 U2.24
  Bottom Layer w7: TP3.1 426,720 486,660 671,660 771,560 771,389.92 v1(885.92,275)
TXD: U1.25 U2.41 | length 970.5
  Top Layer w7: U1.25 v1(711,550) ; U2.41 v1(1270.92,365.47)
  Bottom Layer w7: v1(711,550) 711,447.46 745,413.46 745,337.72 847.72,235 902.28,235 967.8,300.51 1132.8,300.51 1197.76,365.47 v1(1270.92,365.47)
VBAT: BAT1.1 C13.1 Q2.3 U5.3 | length 1031.1
  Top Layer w12: Q2.3 v1(458.83,383.7) ; C13.1 U5.3 v1(665.88,31.3)
  Bottom Layer w7: BAT1.1 BAT1.1@171.1,458.9
  Bottom Layer w12: BAT1.1@171.1,458.9 318.56,458.9 329.66,470 406.65,470 458.83,417.82 v1(458.83,383.7) 458.83,153.89 581.42,31.3 v1(665.88,31.3)
VBUS: C7.1 D1.1 Q2.2 U4.1 U4.3 | length 468
  Top Layer w7: D1.1 317.67,289 343.67,315 Q2.2 Q2.2@374.18,312.72 ; C7.1@313.43,463.9 U4.3 ; Q2.2@378.56,314.7 v1(378.56,343.72) ; v1(378.56,433.9) U4.3 ; U4.1 415.48,538.7 424.18,530 424.18,470 418.08,463.9 U4.3
  Bottom Layer w7: v1@374,340.72 374,343.72 v1@376.28,346 ; v1@378,430.72 378.56,430.16 v1(378.56,343.72)
VUSB: D1.2 D2.2 H1.1 Q2.1 R11.1 U1.8 U3.5 U5.4 | length 1825.3
  Top Layer w7: v1(198.43,680.59) U3.5 ; 639.18,255 651.94,267.76 U1.8
  Top Layer w12: H1.1 220.37,546.18 v1(268.43,594.25) ; R11.1 D1.2 322.46,415 347.65,389.8 Q2.1 410.84,389.8 419.18,381.46 419.18,255 ; D2.2 463.37,150 419.18,194.19 419.18,255 ; U5.4 728.88,62.6 719.18,72.29 719.18,167.2 704.07,182.32 669.07,182.32 639.18,212.2 639.18,255 v1(544.18,255) 419.18,255
  Bottom Layer w7: v1(198.43,680.59) 222.08,680.59 268.46,634.22 v1@268.46,604.22
  Bottom Layer w12: v1(268.43,594.25) 268.43,575.75 293.38,550.81 391.64,550.81 491,451.45 491,348.19 544.18,295 v1(544.18,255)
pads on no net: ANT1.3 ANT1.4 H1.4 U1.1 U1.2 U1.10 U1.11 U1.12 U1.13 U1.14 U1.15 U1.16 U1.17 U1.18 U1.19 U1.20 U1.21 U1.22 U1.23 U1.27 U2.5 U2.6 U2.7 U2.8 U2.10 U2.14 U2.16 U2.18 U2.21 U2.22 U2.25 U2.26 U2.27 U2.28 U2.29 U2.30 U2.31 U2.32 U2.33 U2.38 U2.39 U2.42 U2.44 U2.45 U2.47 U2.48 U3.3 U3.4 U6.2 U6.3 U6.9 U6.13 U6.15 U6.16

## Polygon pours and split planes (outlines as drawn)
GND on Layer 1 (GND) (split plane): 187 vertices, not listed, extent 20.03,19.97 1540.9,969.97
+3.3V on Layer 2 (PWR) (split plane): 187 vertices, not listed, extent 20.03,19.97 1541.9,969.97

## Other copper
Top Layer:
  text "1" at 381.64,245 h40
Bottom Layer:
  text "4" at 371,245 h40
Layer 1 (GND) (plane layer: these items are gaps in the copper):
  pour cut-out: 1546.03,204.99 cw(c1546,210) 1540.98,210 1540.98,776.99 cw(c1545,780) 1545,785.02 1669,785.02 cw(c1669,680) 1774.01,680.03 cw(c1769,680) 1774.01,680 1774.01,310 cw(c1669,310) 1669,204.99 cw(c1669,210) 1668.95,204.99
  lines w10: 1545,780 1669,780 cw(c1669,680) 1769,680 1769,310 cw(c1669,310) 1669,210 1546,210 1546,780
  text "2" at 376.32,245 h40
Layer 2 (PWR) (plane layer: these items are gaps in the copper):
  pour cut-out: 1547.03,206.97 cw(c1547,211.98) 1541.99,211.98 1541.99,778.98 cw(c1546,781.99) 1546,787 1670,787 cw(c1670,681.99) 1775.01,682.02 cw(c1770,681.99) 1775.01,681.99 1775.01,311.98 cw(c1670,311.98) 1670,206.97 cw(c1670,211.98) 1669.96,206.97
  lines w10: 1546,780 1670,780 cw(c1670,680) 1770,680 1770,310 ; 1547,210 1547,780
  text "3" at 376,243.16 h40

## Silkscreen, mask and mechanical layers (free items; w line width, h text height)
Top Overlay:
  text "ESP32 Coin" at 1040,185 h35
  text "Rev1.0" at 1049,27 h35
Bottom Overlay:
  lines w10: 537.95,956.03 cw(c600.41,745.09) 606.21,965.01 ; 1160,965 cw(c1165.8,745.08) 1243.55,950.88
  text "35" at 1332,919 h35
  text "32" at 1347,852 h35
  text "Touch" at 391.64,800 h35 r40
  text "+3.3v" at 1551,696 h35
  text "GND" at 1749,630 h35
  text "SDA" at 1746,323 h35
  text "SCL" at 1551,260 h35
Mechanical 1:
  lines w10: 506.98,35.69 ccw(c583.59,99.97) 586,0 1184,0 ccw(c1186.41,99.97) 1263.02,35.69 ; 507.44,35.24 365,205 ccw(c285,145) 285,245 100,245 cw(c100,345) 0,345 0,645 cw(c100,645) 100,745 231,745 ccw(c231,845) 331,845 331,890 cw(c431,890) 431,990 1346,990 cw(c1346,890) 1446,890 1446,880 ccw(c1546,880) 1546,780 1670,780 cw(c1670,680) 1770,680 1770,310 cw(c1670,310) 1670,210 1456,210 ccw(c1456,110) 1376,170 ; 1262.55,35.24 1375.78,170.18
